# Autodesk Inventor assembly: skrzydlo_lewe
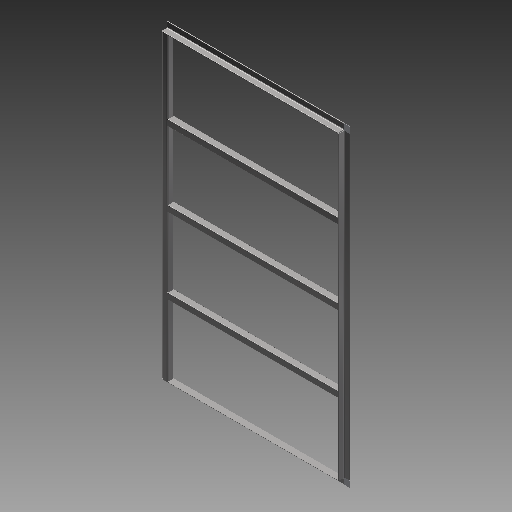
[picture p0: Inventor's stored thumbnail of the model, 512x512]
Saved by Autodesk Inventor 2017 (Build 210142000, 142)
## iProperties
Created: 2020-07
Part Number: skrzydlo_lewe
Document SubType Name: Assembly
Designer: X
Mass: 25997.3 g
Surface Area: 21633.6 cm^2
Volume: 3322.93 cm^3
Density: 7.82361 g/cm^3
_SolveAssemblyDoc: Frame Generator Solve Assembly
_Version: 15.0.0
Author: X
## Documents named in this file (3)
- C:\Users\WindowsX\Desktop\brama\skrzydlo_lewe.iam
- C:\Users\WindowsX\Desktop\brama\skrzydlo bramy.ipt
- C:\Users\WindowsX\Desktop\brama\skrzydlo_lewe\Frame\Frame0001.iam
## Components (3 placed, 2 different names)
1. skrzydlo bramy:1 — Zestawiający:1, Zestawiający:2, Zestawiający:3
2. Frame0001:1 [sub-assembly] — Zestawiający:1, Zestawiający:2, Zestawiający:3, Zestawiający:4, Zestawiający:5
3. skrzydlo bramy:2 — Zestawiający:4, Zestawiający:5
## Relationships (5: Mate 5)
- Zestawiający:1 [Mate]: skrzydlo bramy:1 ↔ Frame0001:1
- Zestawiający:2 [Mate]: skrzydlo bramy:1 ↔ Frame0001:1
- Zestawiający:3 [Mate]: skrzydlo bramy:1 ↔ Frame0001:1
- Zestawiający:4 [Mate]: Frame0001:1 ↔ skrzydlo bramy:2
- Zestawiający:5 [Mate]: Frame0001:1 ↔ skrzydlo bramy:2
